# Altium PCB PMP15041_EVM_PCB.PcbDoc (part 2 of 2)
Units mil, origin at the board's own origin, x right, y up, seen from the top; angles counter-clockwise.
Board outline 2200 x 2100 mil, 4 copper layers (Top Layer, Signal Layer 1, Signal Layer 2, Bottom Layer), stack 60 mil thick; 124 components, 58 nets, 320 pads, 164 vias.
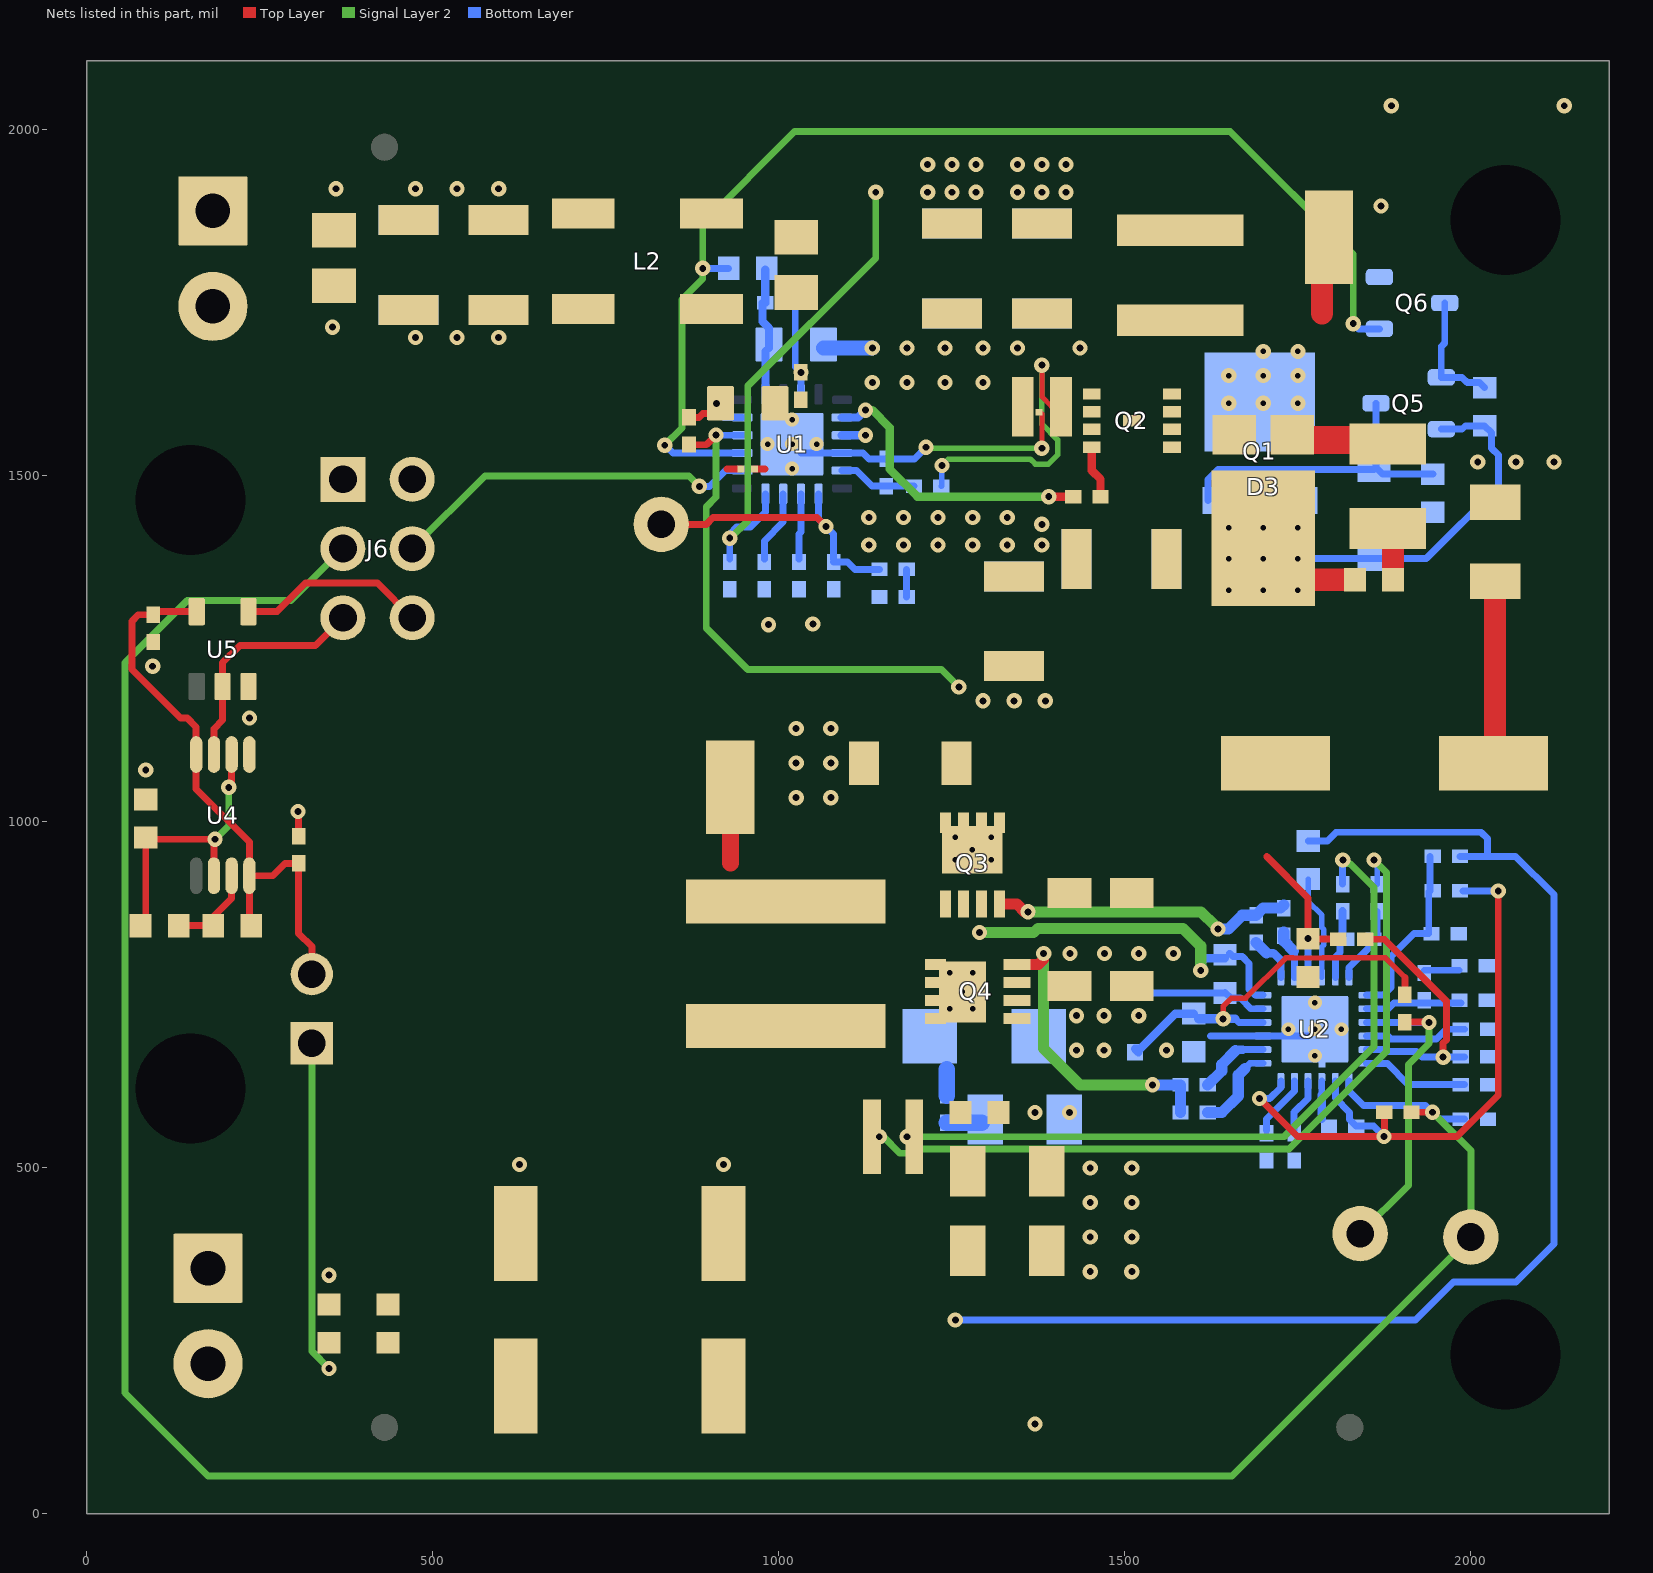
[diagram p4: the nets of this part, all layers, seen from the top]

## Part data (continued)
U5: library part CMP-0051683-1, "Single Inverter, DBV0005A, LARGE T&R", F @ Nom Voltage(Max)(Mhz)=150, Generic Part Number=SN74LVC1G04, ICC @ Nom Voltage(Max)(mA)=0.01, Manufacturer="Texas Instruments", Operating Temperature Range(C)="-40 to 125,-40 to 85", Rating=Catalog, tpd @ Nom Voltage(Max)(ns)=7.5,5.2,4.2,3.7, Voltage(Nom)(V)=1.8,2.5,3.3,5
ZX1: library part AssemblyNote, "This Assembly Note will show in the PcbDoc and associated outputs"
ZZ1: library part CMP-0003616-3
ZZ2: library part CMP-0077236-1
ZZ3: library part CMP-0077237-1
ZZ4: library part CMP-0077238-1

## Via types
v1: diameter 22, hole 10, Top Layer to Bottom Layer, tented both sides, 124 vias
v2: diameter 22, hole 8, Top Layer to Bottom Layer, 27 vias
v3: diameter 20, hole 8, Top Layer to Bottom Layer, 10 vias
v4: diameter 22, hole 10, Top Layer to Bottom Layer, 2 vias
v5: diameter 22, hole 10, Top Layer to Bottom Layer, tented bottom, 1 vias

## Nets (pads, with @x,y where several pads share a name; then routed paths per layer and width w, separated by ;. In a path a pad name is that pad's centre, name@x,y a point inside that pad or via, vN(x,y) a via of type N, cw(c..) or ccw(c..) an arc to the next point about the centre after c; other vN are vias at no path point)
AGND: C17.2 C18.2 C19.1 C21.1 C22.2 C23.2 NT1.1 NT2.1 R12.1 R13.1 U1.11 U1.17@1019.02,1545.98 | length 424.2
  Top Layer w7.5: v1(1380,1540) NT2.1@1380,1590
  Top Layer w10: NT1.1@965,1510 980,1510
  Signal Layer 2 w7.5: v1(1212.63,1541.41) 1214.04,1540 v1(1380,1540)
  Bottom Layer w10: U1.17@1031.81,1533.19 U1.11@1090.87,1533.19 1121.81,1533.19 1130.31,1524.69 C18.2@1155,1524.69 1195.91,1524.69 v1(1212.63,1541.41)
  other v1: 985,1285 1049.02,1285.98
  other v3: 1019.02,1510.55 983.58,1545.98 1019.02,1545.98 1054.45,1545.98 1019.02,1581.42
AGND1: C27.1 C38.2 C39.2 C40.2 C41.2 C42.2 NT3.1 R18.2 R25.1 R32.1 R35.2 U2.3 | length 54.7
  Bottom Layer w10: 1784.45,605.55 U2.3@1784.45,625.59
  Bottom Layer w12: 1784.45,570.87 1784.45,605.55
FB: R27.2 R33.2 R35.1 U2.19 | length 262.8
  Bottom Layer w10: U2.19@1849.41,749.61 1873.82,749.61 1884.61,760.39 1884.61,805.24 1917.8,838.43 1939.17,838.43 R27.2@1939.17,898.58 ; R27.2@1940.98,900.39 R33.2@1940.98,950.24
LM5141_SYNC: J6.3 R15.1 R18.1 TP6.1 U2.1 | length 4008.1
  Top Layer w10: R15.1@1914.29,580.39 v1(1944.61,580.39)
  Signal Layer 2 w10: J6.3@370,1395 295,1320 145,1320 55,1230 55,175 175,55 1655,55 TP6.1@2000,400 2000,525 v1(1944.61,580.39)
  Bottom Layer w10: U2.1@1823.82,625.59 1823.82,611.18 1844.61,590.39 1934.61,590.39 v1(1944.61,580.39) 1954.61,570.39 R18.1@1985.42,570.39 R18.1@1990.98,570.39
LM5150_SYNC: J6.4 U1.1 | length 536.2
  Signal Layer 2 w10: J6.4@470,1395 575,1500 870,1500 v1(885,1485)
  Bottom Layer w10: v1(885,1485) 900,1485 922.6,1507.6 U1.1@947.17,1507.6
NetC1_2: C1.2 R1.2 | length 77.1
  Top Layer w32: R1.2@1880,1423.98 1887.56,1416.42 C1.2@1887.56,1350
NetC7_2: C7.2 R3.2 | length 260.4
  Top Layer w32: C7.2@2035,1087.52 R3.2@2035,1347.91
NetC8_1: C8.1 C9.1 C10.1 C15.1 C16.1 C17.1 L1.1 L2.3 U1.16 | length 715.6
  Signal Layer 2 w10: v1(929.02,1410) 930,1410 955,1435 955,1630 1140,1815 v1(1140,1910)
  Bottom Layer w10: C17.1@929.02,1379.61 v1(929.02,1410) 929.02,1415.98 939.02,1425.98 959.02,1425.98 980.63,1447.6 U1.16@980.63,1474.13
  other v1: 1215,1910 1250,1910 1285,1910 1345,1910 1380,1910 1415,1910 1215,1950 1250,1950 1285,1950 1345,1950 1380,1950 1415,1950
NetC11_1: C11.1 C12.1 C13.1 C14.1 J7.1 L2.4
  other v1: 360,1915 475,1915 535,1915 595,1915
NetC11_2: C11.2 C12.2 C13.2 C14.2 J7.2 L2.1
  other v1: 475,1700 535,1700 595,1700 355,1715
NetC18_1: C18.1 R8.1 U1.12 | length 113.4
  Bottom Layer w10: U1.12@1090.87,1507.6 1112.4,1507.6 1134.68,1485.32 C18.1@1155,1485.32 R8.1@1195,1485.32
NetC19_2: C19.2 R10.1 U1.7 | length 135.6
  Bottom Layer w10: R10.1@1023.62,1750 1023.62,1657.87 v1(1031.81,1649.68) U1.7@1031.81,1617.83
NetC21_2: C21.2 R9.2 U1.4 | length 111
  Top Layer w10: R9.2@870,1584.69 884.69,1584.69 890,1590 910,1590 915.63,1595.63 C21.2@915.63,1605
  Bottom Layer w10: v1(910.06,1604.91) 910.06,1594.94 920.63,1584.37 U1.4@947.17,1584.37
NetC22_1: C22.1 R11.2 TP4.1 U1.13 | length 422
  Top Layer w10: TP4.1@830,1430 895,1430 905,1440 1055,1440 v1(1068.21,1426.79)
  Bottom Layer w10: U1.13@1057.4,1474.13 1057.4,1437.6 v1(1068.21,1426.79) 1079.02,1415.98 C22.1@1079.02,1379.61 ; C22.1@1079.02,1375.67 1099.33,1375.67 1110,1365 R11.2@1145.31,1365
NetC23_1: C23.1 R11.1 | length 40
  Bottom Layer w10: C23.1@1184.68,1325 R11.1@1184.68,1365
NetC30_1: C30.1 D4.1 U2.11 | length 190.4
  Bottom Layer w10: D4.1@1519.61,753.7 1520.47,752.83 C30.1@1644.61,752.83 ; C30.1@1644.61,753.74 1653.11,745.24 1666.87,745.24 1682.19,729.92 U2.11@1699.8,729.92
NetC30_2: C30.2 C31.1 D5.1 L3.1 Q3.1 Q3.2 Q3.3 Q4.5 Q4.6 Q4.7 Q4.8 Q4.9 TP7.1 U2.12 | length 659.9
  Top Layer w24: 930,940 TP7.1@930,1050
  Signal Layer 2 w16: v4(1290,840) 1368.01,840 1374.13,846.13 1583.87,846.13 1609.61,820.39 v1(1609.61,785.39)
  Bottom Layer w10: C30.2@1651.1,810.24 1656.1,805.24 1669.61,805.24 1679.61,795.24 1679.61,757.78 1687.78,749.61 U2.12@1699.8,749.61
  Bottom Layer w12: v1(1609.61,785.39) 1609.61,796.48 1616.08,802.95 C30.2@1644.61,802.95
  Bottom Layer w24: C31.1@1242.76,604.68 1242.76,642.24
  other v2: 1247,730 1280,730 1265.25,754.39 1247,782 1280,782
NetC31_2: C31.2 R29.2 | length 50.5
  Bottom Layer w24: C31.2@1242.76,565.31 R29.2@1293.23,565.31
NetC37_1: C37.1 R34.1 U2.17 | length 93
  Bottom Layer w10: U2.17@1804.13,775.2 1804.13,804.42 1810.98,811.27 C37.1@1810.98,830.37
  Bottom Layer w12: C37.1@1814.61,835.69 R34.1@1814.61,870.71
NetC37_2: C37.2 R30.1 U2.18 | length 102.8
  Bottom Layer w10: U2.18@1823.82,775.2 1823.82,789.45 1856.75,822.38 C37.2@1856.75,830.39 ; C37.2@1864.61,836.77 R30.1@1864.61,870.71
NetC38_1: C38.1 U2.22 | length 149.1
  Bottom Layer w10: U2.22@1849.41,690.55 1880.37,690.55 1884.56,686.36 1950.57,686.36 1964.61,700.39 C38.1@1990.98,700.39
NetC39_1: C39.1 U2.24 | length 154.7
  Bottom Layer w10: U2.24@1849.41,651.18 1849.41,650.61 1879.23,650.61 1909.45,620.39 C39.1@1990.98,620.39
NetC40_1: C40.1 R31.2 U2.20 | length 139.7
  Bottom Layer w10: U2.20@1849.41,729.92 1880.37,729.92 1888.88,738.43 1932.8,738.43 C40.1@1985.55,738.43
NetC41_1: C41.1 U2.5 | length 88.3
  Bottom Layer w10: C41.1@1704.61,554.02 1704.61,570.39 1745.08,610.87 U2.5@1745.08,625.59
NetC42_1: C42.1 R31.1 | length 50
  Bottom Layer w10: R31.1@1932.8,785.67 C42.1@1982.8,785.67
NetC43_1: C43.1 R37.1 U4.2 U4.6 | length 413.4
  Top Layer w10: R37.1@83.5,844.94 85,846.44 C43.1@85,973.45 ; C43.1@86.5,974.94 v1(185,974.94) ; U4.6@183.51,922.13 v1@183.51,973.45 ; v1(205,1049.94) 209.1,1054.05 U4.2@209.1,1097.32
  Signal Layer 2 w10: v1@183.51,973.45 205,995 v1(205,1049.94)
NetC44_2: C44.2 C45.2 J5.2 R36.2 U4.4 U4.8 U5.5 | length 855.1
  Top Layer w10: C44.2@95.99,1299.41 74.41,1299.41 65,1290 65,1220 135,1150 145,1150 157.92,1137.08 U4.4@157.92,1097.32 157.92,1047.79 234.69,971.02 U4.8@234.69,922.13 ; C44.2@96.5,1303.86 U5.5@158.59,1303.86 ; R36.2@234.69,854.69 U4.8@234.69,922.13 ; J5.2@325,780 325,820 305.99,839.01 C45.2@305.99,940.04 286.31,940.04 268.39,922.13 U4.8@234.69,922.13
NetD1_2: D1.2 Q1.4 Q5.3 R5.2 | length 452
  Bottom Layer w10: Q1.4@1620,1464.57 1620,1495 1634.47,1509.47 D1.2@1860,1509.47 ; Q5.3@1862.76,1605 1862.76,1512.22 D1.2@1869.98,1505 ; D1.2@1872.42,1502.56 R5.2@1945,1502.56
NetD3_1: D3.1 D3.2 L1.2 Q1.5 Q2.5 Q2.6 Q2.7 Q2.8 Q2.9 R1.1 TP1.1 | length 253.5
  Top Layer w32: 1785,1735 TP1.1@1785,1852
  Top Layer w40: D3.2@1738.51,1551.93 R1.1@1875,1551.93
  other v2: 1650,1605 1700,1605 1750,1605 1650,1645 1700,1645 1750,1645 1700,1680 1750,1680
NetJ6_5: J6.5 U4.3 U5.2 | length 336.9
  Top Layer w10: U4.3@183.51,1097.32 183.51,1134.57 195.99,1147.05 U5.2@195.99,1193.73 ; U5.2@195.99,1195.59 195.99,1230.04 220.95,1255 330,1255 J6.5@370,1295
NetJ6_6: J6.6 U5.4 | length 274.4
  Top Layer w10: U5.4@233.39,1303.86 275,1303.86 316.14,1345 420,1345 J6.6@470,1295
NetL3_2: L3.2 R22.1 R30.2 | length 1135.4
  Top Layer w10: R22.1@1134.49,545 v1(1145,545)
  Signal Layer 2 w10: v1(1145,545) 1151.24,545 1175.11,521.13 1194.89,521.13 1200.89,527.13 1737.13,527.13 1877.87,667.87 1877.87,927.13 v1(1860,945)
  Bottom Layer w8: v1(1860,945) 1864.61,940.39 R30.2@1864.61,910.08
NetQ2_1: Q2.1 Q2.2 Q2.3 R7.2 R8.2 | length 428.2
  Top Layer w7.5: v1(1380,1660) 1380,1614.44 1394.44,1600 R7.2@1407.56,1600
  Signal Layer 2 w8: v1(1235.51,1515) 1244.88,1524.38 1363.28,1524.38 1370.53,1517.13 1389.47,1517.13 1402.87,1530.53 1402.87,1552.13 1380,1575 v1(1380,1660)
  Bottom Layer w8: R8.2@1234.69,1485 1235.51,1485.82 v1(1235.51,1515)
NetQ2_4: Q2.4 R6.1 | length 76.8
  Top Layer w12: Q2.4@1452.13,1541.61 1452.13,1507.87 1464.68,1495.32 R6.1@1464.68,1470
NetQ3_4: Q3.4 R17.2 R20.1 | length 439.8
  Top Layer w16: Q3.4@1319,881.25 1343.75,881.25 1355,870 v1(1360,870)
  Signal Layer 2 w16: v1(1360,870) 1610,870 1630,850 v1(1634.61,845.39)
  Bottom Layer w16: v1(1634.61,845.39) 1649.61,845.39 1669.29,865.08 R17.2@1689.61,865.08 1699.92,875.39 1724.92,875.39 R20.1@1729.61,880.08
NetQ4_4: Q4.4 R26.2 R28.1 | length 447.5
  Top Layer w16: Q4.4@1343.75,794 1375.33,794 1382.6,801.27 v1(1382.6,810)
  Signal Layer 2 w16: v1(1382.6,810) 1382.6,672.6 1435.2,620 v1(1540,620)
  Bottom Layer w16: v1(1540,620) R28.1@1580.32,620 R26.2@1580.31,580
NetQ5_1: Q5.1 Q6.3 R2.1 | length 178.6
  Bottom Layer w10: Q6.3@1962.24,1750 1962.24,1692.24 1957.24,1687.24 Q5.1@1957.24,1642.4 1987.36,1642.4 1994.76,1635 2012.56,1635 R2.1@2020,1627.56
NetQ6_1: Q6.1 R4.1 U1.2 | length 1714.5
  Signal Layer 2 w10: v1(835,1544.29) 860,1569.29 860,1755 890,1785 v4(890,1800) 890,1865 1022.64,1997.64 1137.36,1997.64 ; 1130,1997.64 1652.23,1997.77 1830,1820 v1(1830,1720)
  Bottom Layer w10: v1(835,1544.29) 835.71,1544.29 846.81,1533.19 U1.2@947.17,1533.19 ; v4(890,1800) R4.1@927.44,1800 ; v1(1830,1720) 1837.4,1712.6 Q6.1@1867.76,1712.6
NetR6_2: R6.2 U1.9 | length 425.8
  Top Layer w12: v1(1390,1470) R6.2@1425.31,1470
  Signal Layer 2 w12: v1(1125,1595) 1135,1595 1160,1570 1160,1510 1200,1470 v1(1390,1470)
  Bottom Layer w12: U1.9@1090.87,1584.37 1114.37,1584.37 v1(1125,1595)
NetR12_2: R12.2 U1.14 | length 95.7
  Bottom Layer w10: R12.2@1029.02,1379.61 1029.02,1415.98 1031.81,1418.78 U1.14@1031.81,1474.13
NetR13_2: R13.2 U1.15 | length 105.8
  Bottom Layer w10: R13.2@979.02,1379.61 979.02,1405.98 1006.22,1433.19 U1.15@1006.22,1474.13
NetR16_2: R16.2 TP5.1 U2.21 | length 471.2
  Top Layer w10: R16.2@1904.61,710.71 v1@1939.13,710.71
  Signal Layer 2 w10: TP5.1@1840,405 1909.61,474.61 1909.61,649.61 1939.61,679.61 v1(1939.61,710.24)
  Bottom Layer w10: U2.21@1849.41,710.24 v1(1939.61,710.24)
NetR17_1: R17.1 U2.13 | length 70.7
  Bottom Layer w10: U2.13@1725.39,775.2 1725.39,799.45
  Bottom Layer w12: 1704.61,810.24 1714.61,810.24 1725.39,799.45
  Bottom Layer w16: R17.1@1689.61,825.71 1704.61,810.71
NetR20_2: R20.2 U2.14 | length 71.4
  Bottom Layer w10: U2.14@1745.08,775.2 1745.08,813.53
  Bottom Layer w16: R20.2@1729.61,840.71 1729.61,827.81 1743.89,813.53
NetR23_2: R23.2 R25.2 U2.23 | length 383
  Top Layer w10: R23.2@1847.48,830.37 1875.04,830.37 1964.61,740.81 1964.61,685 1960,680.39 v1(1960,660)
  Bottom Layer w10: U2.23@1849.41,670.87 1874.78,670.87 1877.16,668.49 1921.35,668.49 1929.61,660.24 1990.83,660.24 R25.2@1990.98,660.39
NetR26_1: R26.1 U2.7 | length 127.2
  Bottom Layer w10: 1673.37,643.45 1681.1,651.18 U2.7@1699.8,651.18
  Bottom Layer w16: R26.1@1619.68,580 1640,580 1663.87,603.87 1663.87,633.95 1673.37,643.45
NetR28_2: R28.2 U2.8 | length 106.1
  Bottom Layer w10: 1670.24,670.87 U2.8@1699.8,670.87
  Bottom Layer w12: 1660.08,670.87 1670.24,670.87
  Bottom Layer w16: R28.2@1619.69,620 1640,640.31 1640,649.6 1660.08,669.68
NetR32_2: R32.2 U2.4 | length 79.9
  Bottom Layer w10: R32.2@1744.61,554.02 1744.61,580.39 1764.76,600.55 U2.4@1764.76,625.59
NetR36_1: R36.1 R37.2 U4.7 | length 133.1
  Top Layer w10: R37.2@132.56,850 R36.1@182.44,850 182.44,862.44 209.1,889.1 U4.7@209.1,922.13
PGND: C3.2 C4.2 C5.2 C6.2 C8.2 C9.2 C10.2 C15.2 C16.2 C20.2 C24.2 C25.2 C26.2 C28.1 C29.1 C32.2 C33.2 C34.2 C35.2 C36.2 C43.2 C44.1 C45.1 C46.2 D5.2 J8.1 L2.2 NT1.2 NT2.2 NT3.2 Q4.1 Q4.2 Q4.3 Q6.2 R3.1 R5.1 R7.1 R24.1 R29.1 U1.10 U2.9 U2.25@1774.61,700.39 U4.1 U5.3 | length 300.7
  Top Layer w10: C45.1@305.99,979.41 v1@305.99,1014.01 ; 925,1510 NT1.2@945,1510
  Bottom Layer w10: 1623.46,690.55 U2.9@1699.8,690.55 U2.25@1764.76,690.55
  Bottom Layer w12: U1.10@1090.87,1558.78 v1(1125,1558.78)
  Bottom Layer w22: C20.2@1064.37,1685 v1(1135,1685)
  other v1: 1370,130 350,345 1450,350 1510,350 1450,400 1510,400 1450,450 1510,450 1450,500 1510,500 625,505 920,505 1370,580 1420,580 1430,670 1470,670 1560,670 1430,720 1470,720 1520,720 1420.63,810 1470.63,810 1520,810 1570,810 305,1015 1025,1035 1075,1035 85,1075 1025,1085 1075,1085 1025,1135 1075,1135 235,1150 95,1225 1130,1400 1180,1400 1230,1400 1280,1400 1330,1400 1380,1400 1380,1430 1130,1440 1180,1440 1230,1440 1280,1440 1330,1440 2010,1520 2065,1520 2120,1520 1135,1635 1185,1635 1240,1635 1295,1635 1185,1685 1240,1685 1295,1685 1345,1685 1435,1685 1870,1890 1885,2035 2135,2035
  other v3: 1774.61,662.01 1736.22,700.39 1774.61,700.39 1812.99,700.39 1774.61,738.78
PVCC: C20.1 R4.2 R10.2 U1.5 | length 182.7
  Bottom Layer w12: R4.2@980.31,1797.76 R10.2@980.31,1750 976.38,1750 976.38,1723.12 985.63,1713.87 C20.1@985.63,1685 ; U1.5@980.63,1617.83 C20.1@980.63,1680
SYNC_Boost: J6.2
SYNC_Buck: J6.1
VCC: C29.2 D4.2 R16.1 U2.10 | length 559.4
  Top Layer w7.5: 1742.68,803.46 1786.48,803.46
  Top Layer w8: v1@1642.05,710.39 1642.05,733.29 1654,745.24 1674.45,745.24 1732.68,803.46 1742.68,803.46 ; 1786.48,803.46 1876.54,803.46 1904.61,775.39
  Top Layer w10: R16.1@1904.61,750.08 1904.61,775.39
  Bottom Layer w10: 1659.61,715.39 1664.76,710.24 U2.10@1699.8,710.24
  Bottom Layer w12: D4.2@1519.61,667.09 1514.61,672.09 1522.09,672.09 1572.95,722.95 C29.2@1599.61,722.95 ; v1(1642.05,715.39) 1659.61,715.39
  Bottom Layer w14: C29.2@1607.17,715.39 v1(1642.05,715.39)
VCCX: R19.1 U2.16 | length 152.8
  Bottom Layer w8: 1764.76,885.24 1784.61,865.39 1784.61,847.43 1787.64,844.4 1787.64,822.26 1784.45,819.07 U2.16@1784.45,775.2 ; 1765,885.47 R19.1@1765,917.44
VDDA: C27.2 R15.2 R27.1 U2.2 U2.6 | length 934.3
  Top Layer w10: v1(1694.61,600.39) 1749.61,545.39 v1(1874.61,545.39) 1979.76,545.39 2039.61,605.24 v1(2039.61,900.24) ; v1@1874.92,545.71 R15.2@1874.92,580.39
  Bottom Layer w10: v1(1694.61,600.39) 1709.33,600.39 1725.39,616.46 U2.6@1725.39,625.59 ; U2.2@1804.13,625.59 1804.13,600.87 1824.74,580.26 1824.74,569.94 C27.2@1834.29,560.39 1859.61,560.39 v1(1874.61,545.39) ; R27.1@1988.39,900.24 v1@2029.61,900.24
VOUTBOOST: C1.1 C3.1 C4.1 C5.1 C6.1 C7.1 C24.1 C25.1 C26.1 C28.2 D1.1 D3.3 Q1.1 Q1.2 Q1.3 Q3.5 Q3.6 Q3.7 Q3.8 Q3.9 Q5.2 R2.2 R9.1 R23.1 U1.3 U2.15 | length 1558.1
  Top Layer w10: R9.1@870,1545.32 870.32,1545 895,1545 v1(909.2,1559.2) ; 1705,950 1764.76,890.24 v5(1764.76,831.73) C28.2@1764.76,831.02 R23.1@1807.46,831.02
  Top Layer w32: D3.3@1759.84,1350 C1.1@1832.44,1350
  Signal Layer 2 w10: v1(909.2,1559.2) 909.2,1469.2 895,1455 895,1280 955,1220 1235,1220 v1(1260,1195)
  Bottom Layer w10: v1(909.2,1559.2) 910,1560 911.22,1558.78 U1.3@947.17,1558.78 ; U2.15@1764.76,775.2 v5(1764.76,831.73) ; 1770.53,1380.53 D1.1@1860,1380.53 1935.53,1380.53 2040,1485 2040,1530 2030,1540 2030,1562.44 R2.2@2020,1572.44 1992.2,1572.44 1987.36,1567.6 Q5.2@1957.24,1567.6
  other v1: 1295,1175 1340,1175 1385,1175
  other v2: 1255,945 1307,945 1279.39,959.75 1255,978 1307,978 1650,1335 1700,1335 1750,1335 1650,1380 1700,1380 1750,1380 1650,1425 1700,1425 1750,1425
VOUTBUCK: C32.1 C33.1 C34.1 C35.1 C36.1 C46.1 J5.1 J8.2 R19.2 R22.2 R24.2 R33.1 R34.2 | length 3400.8
  Signal Layer 2 w10: J5.1@325,680 325,235 v1(350,210) ; v1(1185,545) 1729.72,545 1860,675.28 1860,905 1825,940 v1@1815,940
  Bottom Layer w10: v1(1255,280) 1920,280 1975,335 2065,335 2120,390 2120,895 2064.76,950.24 2023.92,950.24 ; R19.2@1765,972.56 1792.56,972.56 1805,985 2015,985 2023.92,976.08 2023.92,950.24 ; R34.2@1814.61,910.08 v1@1814.61,944.61 ; R33.1@1984.29,950.24 2023.92,950.24
  other v1: 1815,945
pads on no net: FID1.1 FID2.1 FID3.1 MH1.1 MH2.1 MH3.1 MH4.1 U1.6 U1.8 U1.17@995,1521.97 U1.17@995,1570 U1.17@1043.03,1521.97 U1.17@1043.03,1570 U1.A1 U1.A2 U1.A3 U1.A4 U2.25@1749.41,675.2 U2.25@1749.41,725.59 U2.25@1799.8,675.2 U2.25@1799.8,725.59 U4.5 U5.1

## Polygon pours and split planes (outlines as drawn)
NetL3_2 on Top Layer "TOP_LAYER_NETL3_2_P321" (solid, pour order 321): 1141.38,490 1016.08,490 852.52,653.56 852.52,740 1167.48,740 1167.48,657.48 1140,630
VOUTBOOST on Top Layer "TOP_LAYER_VOUTBOOST_P327" (solid, pour order 327): 1547.4,875 1385,875 1385,876.16 1356.16,905 1336.16,925 1226.15,925 1200,951.15 1200,1160 1295,1255 1455,1255 1535,1335 1535,1440.56 1603.91,1509.47 1800,1509.47 1800,1030 1700,930 1585,930
NetC30_2 on Top Layer "TOP_LAYER_NETC30_2_P322" (solid, pour order 322): 1305,905 1305,687.61 1190,687.61 1190,787.48 1133.63,843.85 853.67,843.85 850,847.52 850,970 1135,970 1175,930 1200,905
NetC8_1 on Top Layer "TOP_LAYER_NETC8_1_P326" (solid, pour order 326): 855,2080 855,1855 950,1855 988,1817 1679,1817 1705,1843 1705,2055 1680,2080
VOUTBUCK on Top Layer "Top Layer-No Net 3" (solid, pour order 328): 1190,609.86 1190,335 1120,265 990,265 50,265 0,215 0,85 65,20 1310,20 1310,578.7 1290,598.7 1278.84,609.86
NetC11_1 on Top Layer "TOP_LAYER_NETC11_1_P325" (solid, pour order 325): 45,1830 765,1830 765,1965 650,2080 60,2080 12,2032 12,1863
NetC11_2 on Top Layer "TOP_LAYER_NETC11_2_P324" (solid, pour order 324): 45,1800 765,1800 765,1690 690,1615 50,1615 12,1653 12,1767
NetD3_1 on Top Layer "TOP_LAYER_NETD3_1_P323" (solid, pour order 323): 1485,1510.5 1595,1510.5 1595,1528.27 1805,1528.27 1805,1750 1485,1750
PGND on Top Layer "TOP_LAYER_PGND_P329" (solid, pour order 329): 2200,0 2200,1795 2200,2100 1740,2100 1740,1850 1690,1800 990,1800 955,1765 857.46,1765 850.4,1555 0,1555 0,0
NetQ2_1 on Top Layer "TOP_LAYER_NETQ2_1_P318" (solid, pour order 318): 1470,1555 1396.69,1555 1395,1556.69 1395,1655 1470,1655
AGND on Top Layer "TOP_LAYER_AGND_P319" (solid, pour order 319): 1066.88,1495 1066.88,1612.83 973.12,1612.83 973.12,1495
PGND on Top Layer "TOP_LAYER_PGND_P320" (solid, pour order 320): 741.26,921.26 611.26,921.26 611.26,1078.74 768.74,1078.74 768.74,948.74
VOUTBOOST on Bottom Layer "BOTTOM_LAYER_VOUTBOOST_P345" (solid, pour order 345): 1548.39,876.69 1385.98,876.69 1385.98,877.85 1357.14,906.69 1337.14,926.69 1227.13,926.69 1200.98,952.84 1200.98,1161.69 1295.98,1256.69 1455.98,1256.69 1535.98,1336.69 1535.98,1442.25 1604.89,1511.16 1800.98,1511.16 1800.98,1031.69 1700.98,931.69 1585.98,931.69
PGND on Bottom Layer "BOTTOM_LAYER_PGND_P347" (solid, pour order 347): 2199.51,-0.49 2199.51,1794.51 2199.51,2099.51 1739.51,2099.51 1739.51,1849.51 1689.51,1799.51 989.51,1799.51 954.51,1764.51 856.97,1764.51 849.92,1554.51 -0.49,1554.51 -0.49,-0.49
PGND on Bottom Layer "BOTTOM_LAYER_PGND_P346" (solid, pour order 346): 1494.8,1294.76 1494.8,1775.57 1475.18,1795.2 985.2,1795.2 955.2,1765.2 855,1765.2 855,1273.36 1470.24,1270.32
VOUTBOOST on Bottom Layer "BOTTOM_LAYER_VOUTBOOST_P339" (solid, pour order 339): 1785,1315 1615,1315 1615,1435 1640,1435 1650,1445 1650,1490 1785,1490
AGND on Bottom Layer "BOTTOM_LAYER_AGND_P337" (solid, pour order 337): 895.33,1270 1164.67,1270 1165.33,1269.33 1165.33,1354.33 895.33,1354.33
NetD3_1 on Bottom Layer "BOTTOM_LAYER_NETD3_1_P340" (solid, pour order 340): 1795,1530 1595,1530 1595,1750 1795,1750
AGND1 on Bottom Layer "Top Layer-No Net 4" (solid, pour order 341): 1684.5,576.65 1810,576.65 1810,525 2015,525 2015,808.31 1975,808.31 1975,865 2095,865 2095,465 1684.5,465
NetC30_2 on Bottom Layer "BOTTOM_LAYER_NETC30_2_P338" (solid, pour order 338): 1165,820 1301.41,820.04 1301.41,669.45 1271.96,640 1165,640
NetC8_1 on Bottom Layer "BOTTOM_LAYER_NETC8_1_P344" (solid, pour order 344): 855,2080 855,1855 950,1855 988,1817 1679,1817 1705,1843 1705,2055 1680,2080
NetC11_1 on Bottom Layer "BOTTOM_LAYER_NETC11_1_P343" (solid, pour order 343): 45,1830 765,1830 765,1965 650,2080 60,2080 12,2032 12,1863
NetC11_2 on Bottom Layer "BOTTOM_LAYER_NETC11_2_P342" (solid, pour order 342): 45,1800 765,1800 765,1690 690,1615 50,1615 12,1653 12,1767
AGND on Signal Layer 1 "SIGNAL_LAYER_1_AGND_P330" (solid, pour order 330): 970,1594.57 1070,1594.57 1070,1270 970,1270
PGND on Signal Layer 1 "SIGNAL_LAYER_1_PGND_P333" (solid, pour order 333): 0,2100 2200,2100 2200,0 0,0
NetC11_1 on Signal Layer 1 "SIGNAL_LAYER_1_NETC11_1_P332" (solid, pour order 332): 45,1830 765,1830 765,2080 60,2080 12,2032 12,1863
NetC11_2 on Signal Layer 1 "SIGNAL_LAYER_1_NETC11_2_P331" (solid, pour order 331): 45,1800 765,1800 765,1605 60,1605 12,1653 12,1767
PGND on Signal Layer 2 "SIGNAL_LAYER_2_PGND_P336" (solid, pour order 336): 0,0 0,2100 2200,2100 2200,0
NetC11_1 on Signal Layer 2 "SIGNAL_LAYER_2_NETC11_1_P335" (solid, pour order 335): 45,1830 765,1830 765,2080 60,2080 12,2032 12,1863
NetC11_2 on Signal Layer 2 "SIGNAL_LAYER_2_NETC11_2_P334" (solid, pour order 334): 45,1800 765,1800 765,1605 60,1605 12,1653 12,1767

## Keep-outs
Keep-Out Layer:
  the board outline again, w8
  text ".Layer_Name" at 577,-858.49 h60

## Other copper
Top Layer:
  pour cut-out: 1475,1815 1692,1815 1692,1755 1475,1755
  pour cut-out: 1825,1506.5 1945.12,1506.5 1945.12,1463.5 1825,1463.5
  pour cut-out: 840,840 1134.03,840 1179.8,783.26 1179.8,745 1130,745 840,745
  text ".Layer_Name" at 577,-858.49 h60
Signal Layer 1:
  pour cut-out: -2.48,1555 892.52,1555 892.52,1615 -1.9,1615
  pour cut-out: 840,1605 680,1605 770,1695 770,1960 635,2095 770,2095 855,2095 855,1620
  pour cut-out: 782.12,1800 0,1800 0,1830 782.12,1830
  text "'.Layer_Name'" at 580,-855 h60
Signal Layer 2:
  pour cut-out: -2.48,1555 892.52,1555 892.52,1615 -1.9,1615
  pour cut-out: 776.06,1800 -6.06,1800 -6.06,1830 776.06,1830
  pour cut-out: 785,1605 680,1605 770,1695 770,1960 635,2095 770,2095 855,2095 855,1675
  text "'.Layer_Name'" at 580,-855 h60
Bottom Layer:
  text ".Layer_Name" at 577,-858.49 h60

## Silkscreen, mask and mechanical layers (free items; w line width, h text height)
Top Overlay:
  text "VIN" at 165,1995 h60
  text "+" at 60,1985 h80
  text "-" at 60,1580 h80
  text "'.PRJ_Number'.PCB_Rev" at 500,575 h108.27 r90
  text "-" at 60,445 h80
  text "VOUT" at 145,55 h60
  text "+" at 60,50 h80
  text ".Layer_Name" at 577,-858.49 h60
Bottom Overlay:
  text ".Layer_Name" at 577,-858.49 h60
Top Paste:
  text ".Layer_Name" at 577,-858.49 h60
Bottom Paste:
  text ".Layer_Name" at 577,-858.49 h60
Top Solder:
  text ".Layer_Name" at 577,-858.49 h60
  text ".Layer_Name" at 577,-858.49 h60
Bottom Solder:
  text ".Layer_Name" at 577,-858.49 h60
Drill Guide:
  text ".Layer_Name" at 577,-858.49 h60
M1 Board Outline:
  the board outline again, w10
  text ".Layer_Name" at 577,-858.49 h60
M2 Board Dimensions:
  rectangle: 0,-275 125,-150
  rectangle: 125,-400 500,-275
  lines w7: 0,-275 1000,-275 ; 125,-400 125,-150 ; 250,-400 250,-150 ; 500,-400 500,-150 ; 750,-400 750,-150 ; 0,-400 1000,-400 1000,-150 0,-150 0,-400
  text ".Layer_Name" at 577,-858.49 h60
M3 3D STEP Top:
  text ".Layer_Name" at 577,-858.49 h60
M4 3D STEP Bottom:
  text ".Layer_Name" at 577,-858.49 h60
M5 Assembly Top:
  lines w10: -292,-930.17 6308,-930.17 ; -292,-726.83 6310,-726.83 ; -292,-523.5 -292,-1133.5 3713,-1133.5 6310,-1133.5 6310,-523.5 -291.5,-523.5 -291.5,-1133.5 1284,-1133.5 ; 2173,-1133.5 2173,-523.5 ; 3440,-726.83 3440,-523.5 ; 4280,-726.83 4280,-523.5 ; 4902,-1140 4902,-937.17
  text "COMPONENTS MARKED 'DNP' SHOULD NOT BE POPULATED." at 1153.5,-318.5 h60
  text "ASSEMBLY VARIANT:" at 1153,-434 h60
  text ".VariantName" at 2189,-434 h60
  text "PCB VIEWED FROM TOP SIDE" at -228.5,-655.67 h60
  text "BOARD #:" at 2248,-655.67 h60
  text ".PRJ_Number" at 2793.5,-655.67 h60
  text "REV:" at 3638,-655.67 h60
  text ".PCB_Rev" at 3929.5,-655.67 h60
  text "SVN REV:" at 4476,-655.67 h60
  text ".VersionControl_RevNumber" at 4982,-655.67 h60
  text "TID #:" at 2248,-859 h60
  text ".TID" at 2793.5,-859 h60
  text "PLOT NAME =" at -228.5,-1064.34 h60
  text ".plot_File_Name" at 577,-1064.34 h60
  text "GENERATED    :" at 2250,-1064.34 h60
  text ".Print_Date" at 3119.5,-1064.34 h60
  text ".Print_Time" at 3848.5,-1064.34 h60
  text "TEXAS INSTRUMENTS" at 5113,-1064.34 h60
M6 Assembly Bottom:
  lines w10: -292.5,-727.33 6309.5,-727.33 ; -290.5,-930.67 6309.5,-930.67 ; 1115.5,-1140.5 1115.5,-937.67 ; 1737.5,-727.33 1737.5,-524 ; 2577.5,-727.33 2577.5,-524 ; 3844.5,-1134 3844.5,-524 ; 4733.5,-1134 6309,-1134 6309,-524 -292.5,-524 -292.5,-1134 2304.5,-1134 6309.5,-1134 6309.5,-524
  text "COMPONENTS MARKED 'DNP' SHOULD NOT BE POPULATED." at 6102,-318 h60
  text ".VariantName" at 5058,-434 h60
  text "ASSEMBLY VARIANT:" at 6097,-434 h60
  text ".VersionControl_RevNumber" at 1035.5,-656.17 h60
  text "SVN REV:" at 1541.5,-656.17 h60
  text ".PCB_Rev" at 2088,-656.17 h60
  text "REV:" at 2379.5,-656.17 h60
  text ".PRJ_Number" at 3224,-656.17 h60
  text "BOARD #:" at 3769.5,-656.17 h60
  text "PCB VIEWED FROM BOTTOM SIDE" at 6246,-656.17 h60
  text ".TID" at 3224,-859.5 h60
  text "TID #:" at 3769.5,-859.5 h60
  text "TEXAS INSTRUMENTS" at 904.5,-1064.84 h60
  text ".Print_Time" at 2169,-1064.84 h60
  text ".Print_Date" at 2898,-1064.84 h60
  text "GENERATED    :" at 3767.5,-1064.84 h60
  text ".plot_File_Name" at 5440.5,-1064.84 h60
  text "PLOT NAME =" at 6246,-1064.84 h60
M9 Title Sheet:
  drawing of 57 lines, arcs and shapes, not listed
  text "1" at 739.84,8036.5 h70
  text "2" at 3235.5,8036.5 h70
  text "3" at 5724.84,8036.5 h70
  text "4" at 8231.51,8036.5 h70
  text "5" at 10730.5,8036.5 h70
  text "6" at 13235.5,8036.5 h70
  text "A" at -416.5,6893.5 h70
  text "A" at 14383.5,6893.5 h70
  text "B" at -416.5,4513.5 h70
  text "B" at 14383.5,4513.5 h70
  text "C" at -416.5,2138.5 h70
  text "C" at 14383.5,2138.5 h70
  text "PROJECT TITLE:" at 11343.5,277.5 h45
  text ".PRJ_Title" at 11393.5,144.17 h70
  text "DESIGNED FOR:" at 11343.5,-23.5 h45
  text ".PRJ_Customer" at 11393.5,-163.5 h70
  text "D" at -416.5,-231.5 h70
  text "D" at 14383.5,-231.5 h70
  text "FILE NAME:" at 11343.5,-323.5 h45
  text ".PCB_File_Name_No_Path" at 11393.5,-443.5 h70
  text "Texas Instruments (TI) and/or its licensors do not warrant the accuracy or completeness of this specification" at 6374,-605.34 h45
  text "ENGINEER:" at 11343.5,-613.5 h45
  text "LAYOUT BY:" at 12848.5,-613.5 h45
  text "or any information contained therein. TI and/or its licensors do not warrant that this design will meet" at 6329.01,-718 h45
  text ".PRJ_Engineer" at 11393.5,-768.49 h70
  text ".PCB_Layout" at 12899,-768.49 h70
  text "the specifications, will be suitable for your application or fit for any particular purpose, or will operate in" at 6329.01,-830.67 h45
  text ".Layer_Name" at 577,-858.49 h60
  text "ALTIUM DESIGNER VERSION:" at 12848.5,-923.5 h45
  text "an implementation. TI and/or its licensors do not warrant that the design is production worthy. You should" at 6329.01,-943.33 h45
  text "completely validate and test your design implementation to confirm the system functionality for your application." at 6374,-1056 h45
  text ".print_Scale" at 11393.5,-1056.83 h70
  text ".Application_BuildNumber" at 12899,-1056.83 h70
  text "1" at 739.84,-1263.5 h70
  text "2" at 3235.5,-1263.5 h70
  text "3" at 5724.84,-1263.5 h70
  text "4" at 8231.51,-1263.5 h70
  text "5" at 10730.5,-1263.5 h70
  text "6" at 13235.5,-1263.5 h70
M10 Fab Notes:
  drawing of 189 lines, arcs and shapes, not listed
  text "DESIGN INFORMATION" at 12382.02,6356.17 h60
  text "MIN. TRACK WIDTH:" at 11737.46,6224.05 h60
  text "8" at 12833.7,6224.05 h60
  text "MIL" at 12988.46,6224.05 h60
  text "MIN. CLEARANCE:" at 11737.46,6099.92 h60
  text "0.2" at 12773.7,6099.93 h60
  text "mm" at 12988.46,6099.92 h60
  text "MIN. VIA PAD SIZE:" at 11737.46,5975.8 h60
  text "24" at 12803.71,5975.8 h60
  text "MIL" at 12988.46,5975.8 h60
  text "0.05mm (2MIL)" at 12432.46,5845.9 h60
  text "MINIMUM ANNULAR RING" at 11408.23,5837.67 h60
  text "EXTERNAL" at 13140.46,5837.67 h60
  text "PER" at 11608.23,5727.55 h60
  text "IPC-D-275 CLASS 2 LEVEL C" at 11828.23,5727.54 h60
  text "MIL, HOLES" at 13316.46,5627.07 h60
  text "+/-" at 12924,5618.48 h60
  text "+/-" at 13778,5618.48 h60
  text "REGISTRATION TOLERANCES:" at 11408.23,5617.42 h60
  text "METAL" at 12608,5617.42 h60
  text "5" at 13184.2,5617.42 h60
  text "3" at 14017.2,5617.42 h60
  text "MIL" at 14133.46,5617.42 h60
  text "HOLE SIZE TOLERANCE (UNLESS OTHERWISE SPECIFIED):" at 11408.23,5519.1 h60
  text "+/-" at 13778,5516.23 h60
  text "3" at 14017.2,5515.17 h60
  text "MIL" at 14133.46,5515.17 h60
  text "MATERIAL:" at 11333.46,5377.52 h60
  text "FR-4 High Tg" at 12319.9,5249 h60
  text "X" at 12175.46,5241.01 h60
  text "FR-408" at 11754.46,5236.49 h60
  text "OTHER" at 13242.46,5236.49 h60
  text "62 MIL (1.6mm) +/-10%" at 12074.56,5093.46 h60
  text "X" at 11954.46,5091.01 h60
  text "THICKNESS:" at 11408.23,5085.24 h60
  text "OTHER" at 13359.46,5085.24 h60
  text "TOLERANCE:" at 11408.23,4946.92 h60
  text "X" at 12256.46,4946.92 h60
  text "ANSI IPC-6012 TYPE 3 CLASS 2" at 12434.48,4946.92 h60
  text "OTHER +/-" at 12434.46,4802.73 h60
  text "BOW & TWIST:" at 11408.23,4657.54 h60
  text "X" at 12256.46,4657.54 h60
  text "ANSI IPC-6012 TYPE 3 CLASS 2" at 12434.48,4657.54 h60
  text "OTHER +/-" at 12434.46,4510.85 h60
  text "DRILLING:" at 11333.46,4380.23 h60
  text "NC_DRILL FILES" at 13094.46,4275.04 h60
  text "REFERENCE:" at 11408.23,4271.1 h60
  text "X" at 12065.46,4271.01 h60
  text "AS SHOWN" at 12243.46,4271.1 h60
  text "X" at 12966.46,4271.1 h60
  text "OTHER" at 13392.46,4128.85 h60
  text "PTH COPPER THICKNESS:" at 11407.91,4125.32 h60
  text "X" at 12547.14,4125.32 h60
  text "20-30 um" at 12675.14,4125.32 h60
  text "BOARD FINISH:" at 11333.46,3977.73 h60
  text "SILKSCREEN:" at 11488.68,3867.6 h60
  text "X" at 12446.46,3867.6 h60
  text "TOP" at 12563.46,3867.6 h60
  text "X" at 12956.46,3867.6 h60
  text "BOTTOM" at 13074.46,3867.6 h60
  text "SILKSCREEN COLOR:" at 11488.68,3712.41 h60
  text "X" at 12445.46,3712.41 h60
  text "WHITE" at 12563.46,3712.41 h60
  text "OTHER" at 13074.46,3712.41 h60
  text "X" at 12576.46,3568.96 h60
  text "GREEN" at 12694.46,3568.96 h60
  text "OTHER" at 13312.46,3568.96 h60
  text "SOLDER RESIST COLOR:" at 11488.68,3562.1 h60
  text "X" at 12576.46,3414.71 h60
  text "MATTE" at 12694.46,3414.71 h60
  text "SEMI-GLOSS" at 13312,3414.07 h60
  text "IMMERSION GOLD (ENIG)" at 12394.46,3241.94 h60
  text "ENEPIG" at 13732,3234.72 h60
  text "SURFACE FINISH:" at 11333.46,3233.72 h60
  text "IMM. TIN/SILVER OR EQUIV" at 11663,3096.4 h60
  text "X" at 11510,3095 h60
  text "OTHER" at 13094.46,3092.47 h60
  text "ARRAY/PANEL:" at 11333.46,2937.09 h60
  text "X" at 12210,2930 h60
  text "CUT AND TRIM PER M1 BOARD OUTLINE" at 12394.46,2928.87 h60
  text "N.C. ROUTE" at 12394.46,2792.9 h60
  text "V. SCORE" at 13260.46,2792.9 h60
  text "CERTIFICATION:" at 11333.46,2663.77 h60
  text "MATERIALS AND WORKMANSHIP FOR ALL PCBS" at 12058.46,2663.77 h60
  text "TO MEET OR EXCEED THE REQUIREMENTS OF:" at 12058.46,2569.71 h60
  text "X" at 11695.97,2441.08 h60
  text "ANSI IPC-A-600F CLASS ->" at 11823.96,2441.08 h60
  text "X" at 13471.97,2441.08 h60
  text "2" at 13581.96,2441.08 h60
  text "1" at 13266.96,2439.58 h60
  text "3" at 13935.96,2439.58 h60
  text "X" at 12507.97,2293.39 h60
  text "RoHS" at 12635.96,2293.39 h60
  text "OTHER" at 13280.36,2293.39 h60
  text "PER ORDER" at 13677.42,2293.39 h60
  text "ALL BOARDS MUST MEET OR EXCEED UL94-V0 REQUIREMENTS." at 11361,2139.57 h60
  text "PCB MUST BEAR THE UL94V-0 UL REGISTERED MATERIAL ID NUMBER" at 11361,2023.5 h60
  text "ADDITIONAL REQUIREMENTS:" at 11333.46,1854.08 h60
  text "MICROSECTION:" at 11408.23,1746.95 h60
  text "YES" at 12313.96,1746.95 h60
  text "REQUIRED" at 13175.46,1602.62 h60
  text "BARE BOARD ELEC. TEST:" at 11408.23,1599.76 h60
  text "NONE" at 12713.96,1599.76 h60
  text "X" at 13057.46,1599.76 h60
  text "PER ORDER" at 13767.46,1599.76 h60
  text "XX MIL VIAS REQUIRE NON-CONDUCTIVE FILL AND PLANARIZE" at 11576.38,1394.82 h59
  text "XX MIL VIAS REQUIRE CONDUCTIVE FILL AND PLANARIZE" at 11584.38,1290.84 h60
  text "OUTER XX MIL TRACES REQUIRE 50 OHM SINGLE-ENDED IMPEDANCE" at 11583.39,1127.46 h58
  text "LAYER 2 & 3 (INNER LAYERS) XX MIL WIDE, XX MIL SPACE / TRACES REQUIRE 100 OHM DIFFERENTIAL IMPEDANCE" at 11575.39,891.74 h60
  text ".Layer_Name" at 577,-858.49 h60
M11 Gerber Information:
  lines w10: -292,-930.17 6308,-930.17 ; -292,-726.83 6310,-726.83 ; -292,-523.5 -292,-1133.5 3713,-1133.5 6310,-1133.5 6310,-523.5 -291.5,-523.5 -291.5,-1133.5 1284,-1133.5 ; 2173,-1133.5 2173,-523.5 ; 3440,-726.83 3440,-523.5 ; 4280,-726.83 4280,-523.5 ; 4902,-1140 4902,-937.17
  text "ALL ARTWORK VIEWED FROM TOP SIDE" at -228.5,-655.67 h60
  text "BOARD #:" at 2248,-655.67 h60
  text ".PRJ_Number" at 2793.5,-655.67 h60
  text "REV:" at 3638,-655.67 h60
  text ".PCB_Rev" at 3929.5,-655.67 h60
  text "SVN REV:" at 4476,-655.67 h60
  text ".VersionControl_RevNumber" at 4982,-655.67 h60
  text "LAYER NAME =" at -228.5,-858.49 h60
  text "TID #:" at 2248,-859 h60
  text ".TID" at 2793.5,-859 h60
  text "PLOT NAME =" at -228.5,-1064.34 h60
  text ".plot_File_Name" at 577,-1064.34 h60
  text "GENERATED    :" at 2250,-1064.34 h60
  text ".Print_Date" at 3119.5,-1064.34 h60
  text ".Print_Time" at 3848.5,-1064.34 h60
  text "TEXAS INSTRUMENTS" at 5113,-1064.34 h60
M12 Stackup:
  drawing of 295 lines, arcs and shapes, not listed
  text "Layer" at 9797.84,7830 h60
  text "Name" at 10207.76,7830 h60
  text "Material" at 11147.5,7830 h60
  text "Thickness" at 12007.26,7830 h60
  text "Constant" at 12657.1,7830 h60
  text "Board Layer Stack" at 13226.96,7830 h60
  text "1" at 9797.84,7710 h60
  text "Top Overlay" at 10207.76,7710 h60
  text "2" at 9797.84,7590 h60
  text "Top Solder" at 10207.76,7590 h60
  text "Solder Resist" at 11147.5,7590 h60
  text "0.40mil" at 12007.26,7590 h60
  text "3.5" at 12657.1,7590 h60
  text "3" at 9797.84,7470 h60
  text "Top Layer" at 10207.76,7470 h60
  text "Copper" at 11147.5,7470 h60
  text "2.00mil" at 12007.26,7470 h60
  text "4" at 9797.84,7350 h60
  text "Dielectric1" at 10207.76,7350 h60
  text "FR-4" at 11147.5,7350 h60
  text "10.00mil" at 12007.26,7350 h60
  text "4.8" at 12657.1,7350 h60
  text "5" at 9797.84,7230 h60
  text "Signal Layer 1" at 10207.76,7230 h60
  text "Copper" at 11147.5,7230 h60
  text "2.00mil" at 12007.26,7230 h60
  text "6" at 9797.84,7110 h60
  text "Dielectric 2" at 10207.76,7110 h60
  text "32.00mil" at 12007.26,7110 h60
  text "4.2" at 12657.1,7110 h60
  text "7" at 9797.84,6990 h60
  text "Signal Layer 2" at 10207.76,6990 h60
  text "Copper" at 11147.5,6990 h60
  text "2.00mil" at 12007.26,6990 h60
  text "8" at 9797.84,6870 h60
  text "Dielectric 3" at 10207.76,6870 h60
  text "10.00mil" at 12007.26,6870 h60
  text "4.2" at 12657.1,6870 h60
  text "9" at 9797.84,6750 h60
  text "Bottom Layer" at 10207.76,6750 h60
  text "Copper" at 11147.5,6750 h60
  text "2.00mil" at 12007.26,6750 h60
  text "10" at 9797.84,6630 h60
  text "Bottom Solder" at 10207.76,6630 h60
  text "Solder Resist" at 11147.5,6630 h60
  text "0.40mil" at 12007.26,6630 h60
  text "3.5" at 12657.1,6630 h60
  text "11" at 9797.84,6510 h60
  text "Bottom Overlay" at 10207.76,6510 h60
  text ".Layer_Name" at 577,-858.49 h60
M13 Component Bodies Top:
  text ".Layer_Name" at 577,-858.49 h60
M14 Component Bodies Bottom:
  text ".Layer_Name" at 577,-858.49 h60
M15 Courtyards Top:
  text ".Layer_Name" at 577,-858.49 h60
M16 Courtyards Bottom:
  text ".Layer_Name" at 577,-858.49 h60
Drill Drawing:
  circle w10: c5363.63,3266.5 r27.59
  lines w10: 5336.04,2742.2 5336.04,2755.99 5349.83,2769.79 5336.04,2783.59 5336.04,2797.39 5349.83,2797.39 5363.63,2783.59 5377.43,2797.39 5391.23,2797.39 5391.23,2783.59 5377.43,2769.79 5391.23,2755.99 5391.23,2742.2 5377.43,2742.2 5363.63,2755.99 5349.83,2742.2 5336.04,2742.2 ; 5336.04,2921.56 5391.23,2921.56 5363.63,2866.37 5336.04,2921.56 ; 5336.04,2990.55 5391.23,2990.55 5391.23,3045.74 5336.04,3045.74 5336.04,2990.55 ; 5336.04,3128.52 5349.83,3128.52 5363.63,3114.72 5377.43,3128.52 5391.23,3128.52 5377.43,3142.32 5391.23,3156.12 5377.43,3156.12 5363.63,3169.91 5349.83,3156.12 5336.04,3156.12 5349.83,3142.32 5336.04,3128.52
  lines w12: 5286,2704.94 8516.52,2704.94 ; 5286,3325.82 8516.52,3325.82 ; 5623.86,2580.77 5623.86,3450 ; 5955.86,2580.77 5955.86,3450 ; 6592.42,2580.77 6592.42,3450 ; 6851.53,2580.77 6851.53,3450 ; 7226.68,2580.77 7226.68,3450 ; 7950.06,2580.77 7950.06,3450 ; 5286,2580.77 8516.52,2580.77 8516.52,3450 5286,3450 5286,2580.77
  text "Symbol" at 5360.51,3363.08 h72
  text "Quantity" at 5661.11,3363.08 h72
  text "Finished Hole Size" at 5993.12,3363.08 h72
  text "Plated" at 6629.67,3363.08 h72
  text "Hole Type" at 6888.78,3363.08 h72
  text "Drill Layer Pair" at 7263.93,3363.08 h72
  text "Hole Tolerance" at 7987.32,3363.08 h72
  text "4" at 5661.11,3238.9 h60
  text "159.00mil (4.039mm)" at 5993.12,3238.9 h60
  text "NPTH" at 6629.67,3238.9 h60
  text "Round" at 6888.78,3238.9 h60
  text "Top Layer - Bottom Layer" at 7263.93,3238.9 h60
  text "37" at 5661.11,3114.72 h60
  text "8.00mil (0.203mm)" at 5993.12,3114.72 h60
  text "PTH" at 6629.67,3114.72 h60
  text "Round" at 6888.78,3114.72 h60
  text "Top Layer - Bottom Layer" at 7263.93,3114.72 h60
  text "127" at 5661.11,2990.55 h60
  text "10.00mil (0.254mm)" at 5993.12,2990.55 h60
  text "PTH" at 6629.67,2990.55 h60
  text "Round" at 6888.78,2990.55 h60
  text "Top Layer - Bottom Layer" at 7263.93,2990.55 h60
  text "11" at 5661.11,2866.37 h60
  text "40.00mil (1.016mm)" at 5993.12,2866.37 h60
  text "PTH" at 6629.67,2866.37 h60
  text "Round" at 6888.78,2866.37 h60
  text "Top Layer - Bottom Layer" at 7263.93,2866.37 h60
  text "4" at 5661.11,2742.2 h60
  text "50.00mil (1.270mm)" at 5993.12,2742.2 h60
  text "PTH" at 6629.67,2742.2 h60
  text "Round" at 6888.78,2742.2 h60
  text "Top Layer - Bottom Layer" at 7263.93,2742.2 h60
  text "183 Total" at 5661.11,2618.02 h60
  text ".Layer_Name" at 577,-858.49 h60
M17 Embedded Cavity:
  text ".Layer_Name" at 577,-858.49 h60
M18 Embedded Assembly:
  text ".Layer_Name" at 577,-858.49 h60
M19 Embedded Keepout:
  text ".Layer_Name" at 577,-858.49 h60

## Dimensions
0,-400 to 1000,-400 on M2 Board Dimensions
0,0 to 2200,0 on M2 Board Dimensions
0,0 to 0,2100 on M2 Board Dimensions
